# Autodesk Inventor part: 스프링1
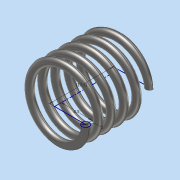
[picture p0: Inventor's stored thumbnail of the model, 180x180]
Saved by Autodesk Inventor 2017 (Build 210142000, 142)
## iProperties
Part Number: 스프링1
Material: 스테인레스 스틸
Document SubType Name: Modeling
Designer: MRC
Density: 8 g/cm^3
Appearance: 반연마
Mass: 6.55763 g
Surface Area: 16.7052 cm^2
Volume: 0.819704 cm^3
Author: MRC
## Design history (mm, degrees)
sketch "스케치1"
  geometry: L1 (0, 0)-(0, 17.5); L2 (0, 0)-(8.5, 0); L3 (0, 17.5)-(8.5, 17.5); C1 r 1 at (8.5, 0)
  constraints: 6 end point, 2 horizontal, 1 centre point, 1 coincident, 1 vertical
  dimensions: "d0" = 17.5 distance of L1.start L1.end (derived); "d1" = 8.5 distance of L1.start L2.end; "d2" = 2 diameter of C1
feature "코일1" pitch "d3" = 10; turns "d5" = 5; dims "d4" = 17.5 (= d0), "d6" = 0, angle "d7" = 90 deg, angle "d8" = 90 deg, "d9" = 0, "d10" = 0
sketch "스케치2"
  geometry: L1 (17.5, 13.489)-(0, 13.489); L2 (0, 13.489)-(0, -13.489); L3 (0, -13.489)-(17.5, -13.489); L4 (17.5, -13.489)-(17.5, 13.489); 2 further points
  constraints: 8 end point, 2 parallel, 1 coincident, 1 horizontal, 1 midpoint, 1 perpendicular
  dimensions: "d11" = 17.5 distance of L2.end L3.end (= d0)
extrude "돌출1" sketch "스케치2" stored distance "d12" = 0; taper "d13" = 0 deg
node "솔리드1"
